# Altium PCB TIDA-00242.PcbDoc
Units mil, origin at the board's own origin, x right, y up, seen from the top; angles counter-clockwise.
Board outline 1000 x 1000 mil, 2 copper layers (Top Layer, Bottom Layer), stack 40.8 mil thick; 41 components, 18 nets, 113 pads, 38 vias.
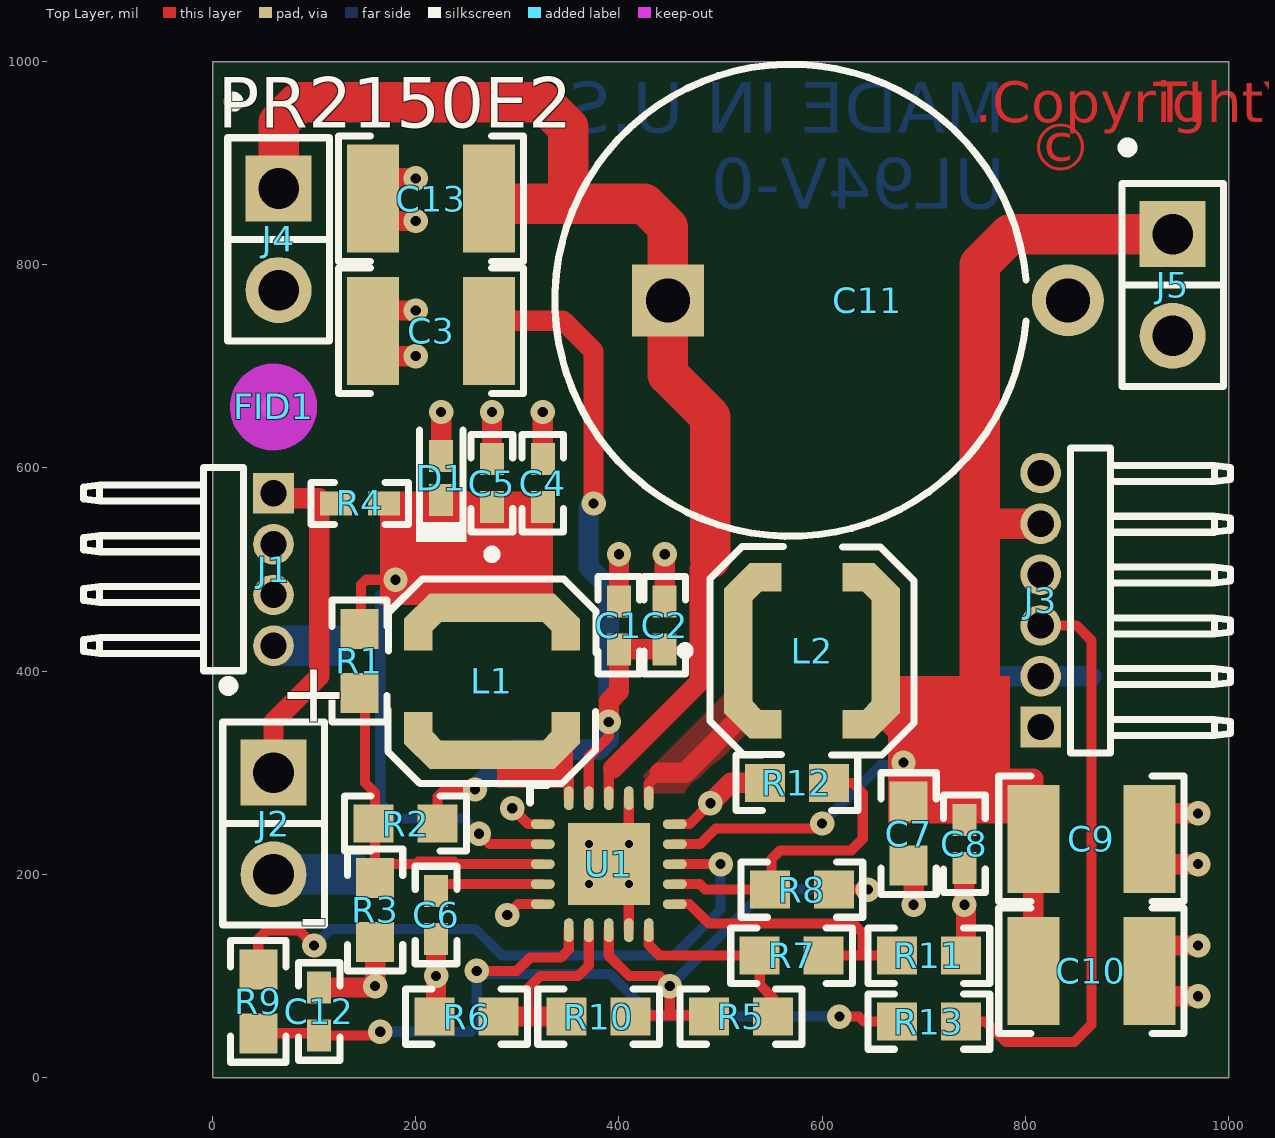
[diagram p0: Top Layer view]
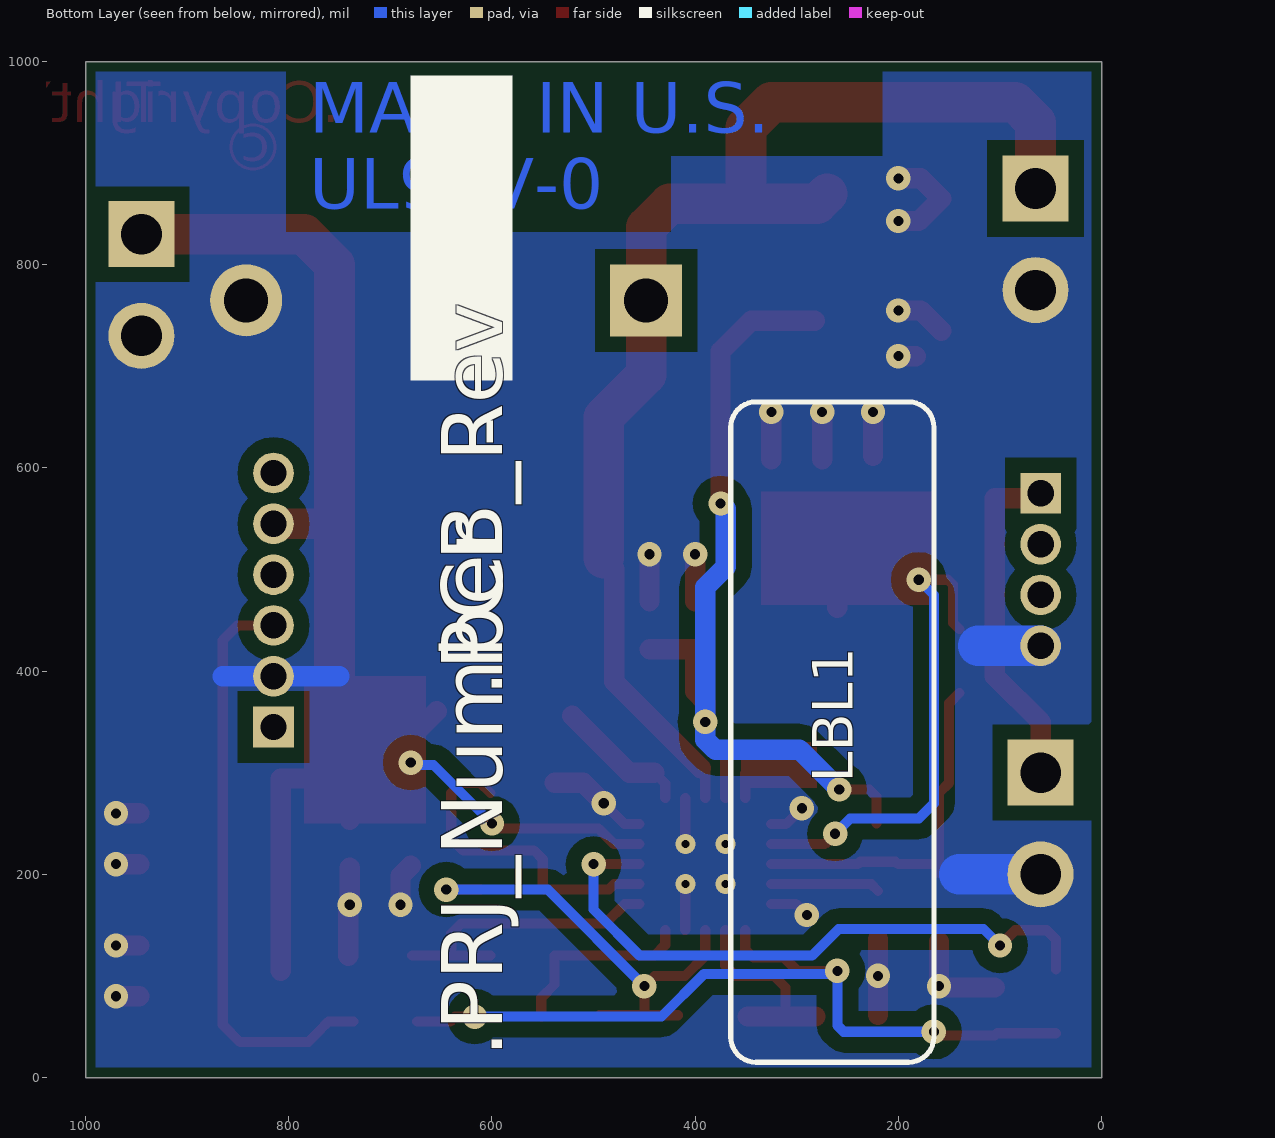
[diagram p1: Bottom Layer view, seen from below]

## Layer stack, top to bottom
Top Layer: signal copper 1.4
Dielectric: core 38, FR-4, Dk 4.8
Bottom Layer: signal copper 1.4

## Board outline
0,0 0,1000 1000,1000 1000,0 0,0

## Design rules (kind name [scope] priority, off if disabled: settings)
AcuteAngle [All] p1: minimum=4.50000000000000E+0001 checktracksonly=FALSE
AssemblyTestPointUsage [All] p1: valid=2
Clearance Clearance_BoardEdge_MountingHoles [OnCopper and InComponentClass('Mounting Holes') vs IsKeepOut] p1: gap=20
Clearance Clearance_BoardEdge_Poly [OnCopper and InPoly vs IsKeepOut] p2: gap=25
Clearance Clearance_BoardEdge [OnCopper and Not InComponentClass('Logo') and not InComponentClass('FiducialMark') and not InRegion(1000,500,4000,800) and Not IsKeepout vs IsKeepOut] p3: gap=20
Clearance Clearance_Poly [InPolygon] p4: gap=15
Clearance [All] p5: gap=8
ComponentClearance ComponentClearance_Logo [InComponentClass('Logo')] p1: gap=20 collisioncheckmode=3 verticalgap=10 showdistances=FALSE
ComponentClearance ComponentClearance_ScrewToNut [(HasFootprint('NY PMS 440 0025 PH')) vs (HasFootprint('Keystone_1902C'))] p2: gap=10 collisioncheckmode=3 verticalgap=10 showdistances=FALSE
ComponentClearance ComponentClearance_MountingHoles [InComponentClass('Mounting Holes')] p3: gap=20 collisioncheckmode=3 verticalgap=100000 showdistances=FALSE
ComponentClearance ComponentClearance_SmallPassives [HasFootprint('0201*') or HasFootprint('0402*') or HasFootprint('0508') or HasFootprint('0603*') or HasFootprint('0612') or HasFootprint('0805*') or HasFootprint('0815*') or HasFootprint('0830*') or HasFootprint('1206*') or HasFootprint('1210*') or HasFootprint('1808*') or HasFootprint('1812*') or HasFootprint('1825*') or HasFootprint('2010*') or HasFootprint('2220*') or HasFootprint('2225*') or HasFootprint('2512*') or HasFootprint('2728*') or HasFootprint('3518*') vs HasFootprint('0201*') or HasFootprint('0402*') or HasFootprint('0508') or HasFootprint('0603*') or HasFootprint('0612') or HasFootprint('0805*') or HasFootprint('0815*') or HasFootprint('0830*') or HasFootprint('1206*') or HasFootprint('1210*') or HasFootprint('1808*') or HasFootprint('1812*') or HasFootprint('1825*') or HasFootprint('2010*') or HasFootprint('2220*') or HasFootprint('2225*') or HasFootprint('2512*') or HasFootprint('2728*') or HasFootprint('3518*')] p4: gap=20 collisioncheckmode=3 verticalgap=10 showdistances=FALSE
ComponentClearance ComponentClearance_THtoSMT [IsThruComponent vs IsSMTComponent] p5: gap=20 collisioncheckmode=3 verticalgap=20 showdistances=FALSE
ComponentClearance ComponentClearance_THtoTH [IsThruComponent vs IsThruComponent] p6: gap=20 collisioncheckmode=3 verticalgap=20 showdistances=FALSE
ComponentClearance [All] p7: gap=20 collisioncheckmode=3 verticalgap=10 showdistances=FALSE
DiffPairsRouting [All] p1: maxlimit=100 minlimit=10 mostfreqgap=10 maxuncoupledlength=1000
FabricationTestPointUsage TestPointUsage [All] p1: valid=2 allowmultiple=FALSE
FabricationTestpoint Testpoint [All] p1: side=3 testpointundercomponent=TRUE minsize=40 maxsize=100 preferedsize=60 minholesize=0 maxholesize=40 preferedholesize=32 testpointgrid=1 allowsidetop=TRUE allowsidebottom=TRUE usegrid=TRUE gridtolerance=0.01
FanoutControl Fanout_LCC [IsLCC] p1: bgadir=Out bgaviamode=Centered fanoutstyle=Auto fanoutdirection=Alternating viagrid=1 // Fanout_LCC (Default Rule)
FanoutControl Fanout_BGA [IsBGA] p2: bgadir=Out bgaviamode=Centered fanoutstyle=Auto fanoutdirection=Alternating viagrid=1 // Fanout_BGA (Default Rule)
FanoutControl Fanout_Default [All] p4: bgadir=Out bgaviamode=Centered fanoutstyle=Auto fanoutdirection=Alternating viagrid=1 // Fanout_Default (Default Rule)
FanoutControl Fanout_Small [(CompPinCount < 5)] p5: bgadir=Out bgaviamode=Centered fanoutstyle=Auto fanoutdirection=OutThenIn viagrid=1 // Fanout_Small (Default Rule)
HoleSize [All] p1: absolutevalues=TRUE maxlimit=251 minlimit=8 maxpercent=80.000 minpercent=20.000
MinimumAnnularRing [All] p1: minimumring=9
MinimumSolderMaskSliver MinimumSolderMaskSliver_Logo [InComponentClass('Logo') vs InComponentClass('Logo')] p1: minsoldermaskwidth=0.7
MinimumSolderMaskSliver [All] p2: minsoldermaskwidth=4
PlaneConnect [All] p1: planeconnectstyle=Relief reliefexpansion=10 reliefentries=4 reliefconductorwidth=10 reliefairgap=10
PolygonConnect [All] p1: connectstyle=Direct reliefconductorwidth=10 reliefentries=4 polygonreliefangle="90 Angle" airgapwidth=10
RoutingVias [All] p1: holewidth=16 width=34 viastyle="Through Hole" minholewidth=8 minwidth=26 maxholewidth=40 maxwidth=65
SMDToCorner [All] p1: distance=30000
SilkToSilkClearance [All] p1: silktosilkclearance=5
SilkscreenOverComponentPads [All] p1: minsilkscreentomaskgap=5
SolderMaskExpansion [All] p1: expansion=3
Width [All] p1: maxlimit=100 minlimit=6 preferedwidth=10 checkconnectedcopper=TRUE
14 further rules are at their usual default settings.

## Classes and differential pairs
component class "PR2150E2 sheet 2": C1 C2 C3 C5 C6 C7 C8 C9 C10 C11 C12 C13 D1 J1 J2 J3 J4 J5 L1 L2 R1 R2 R3 R4 R5 R6 R7 R8 R9 R10 R11 R13 U1
component class "PR2150E2 sheet 3": FID1 LBL1 ZZ1 ZZ2 ZZ3 ZZ4
component class FiducialMark: FID1
component class AssemblyNote: ZZ1 ZZ2 ZZ3 ZZ4
component class Label: LBL1

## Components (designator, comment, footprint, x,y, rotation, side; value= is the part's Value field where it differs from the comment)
C1 "C1005X5R0J475M050BC" 0402 400,445 r90 top
C2 "GRM155R71A104KA01D" 0402 445,445 r90 top
C3 "C1210C107M9PACTU" 1210 215,735 r180 top (schematic designator C4)
C4 "GRM155R71A104KA01D" 0402 325,585 r90 top
C5 "C1005X5R0J475M050BC" 0402 275,585 r90 top
C6 "GRM155R61A103KA01D" 0402 220,160 r270 top
C7 "CL10A226MP8NUNE" 0603 685,240 r270 top
C8 "GRM155R71A104KA01D" 0402 740,230 r270 top
C9 "C1210C107M9PACTU" 1210 865,235 r0 top
C10 "C1210C107M9PACTU" 1210 865,105 r0 top
C11 "DX-5R5H473U" DX-H_1150x500 645,765 r0 top
C12 "C1005X5R0J105M" 0402 105,65 r90 top
C13 "C1210C107M9PACTU" 1210 215,865 r180 top
D1 "BZT52C4V7T-7" SOD-523 225,590 r90 top
FID1 "Fiducial" Fiducial6.4-20 60,660 r0 top
J1 "GRPB041VWCN-RC" Sullins_GRPB041VWCN 60,500 r270 top
J2 "90120-0122" CONN_90120-0122 60,250 r270 top
J3 "GRPB061VWCN-RC" Sullins_GRPB061VWCN 815,470 r90 top
J4 "90120-0122" CONN_90120-0122 65,825 r270 top
J5 "90120-0122" CONN_90120-0122 945,780 r270 top
L1 "LPS4018-223MLB" LPS4018 275,390 r270 top
L2 "LPS4018-103MLB" LPS4018 590,420 r0 top
LBL1 "Size: 0.65\" x 0.20 \"" Label_650x200 265,340 r90 bottom
R1 "ERJ-3GEY0R00V" 0603 144.61,409.87 r270 top
R2 "ERJ-3GEY0R00V" 0603 190,250 r0 top
R3 "ERJ-3GEY0R00V" 0603 160,165 r90 top
R4 "CRCW0402100RJNED" 0402 145,565 r0 top
R5 "CRCW06033M01FKEA" 0603 520,60 r180 top
R6 "CRCW06035M62FKEA" 0603 250,60 r0 top
R7 "CRCW06035M90FKEA" 0603 570,120 r180 top
R8 "CRCW06037M87FKEA" 0603 580,185 r0 top
R9 "CRCW06031M24FKEA" 0603 45,75 r90 top
R10 "CRCW06037M32FKEA" 0603 380,60 r0 top
R11 "CRCW06034M02FKEA" 0603 705,120 r180 top (schematic designator R12)
R12 "CRCW06035M36FKEA" 0603 575,290 r0 top
R13 "ERJ-3GEY0R00V" 0603 705,55 r0 top
U1 "BQ25570RGR" RGR0020A 390,210 r0 top
ZZ1 "This Assembly Note is for PCB labels only" AssemblyNoteLabel 205,2328 r0 top
ZZ2 "This Assembly Note will show in the PcbDoc and associated outputs" AssemblyNote 205,2219.11 r0 top
ZZ3 "This Assembly Note will show in the PcbDoc and associated outputs" AssemblyNote 205,2130.56 r0 top
ZZ4 "This Assembly Note will show in the PcbDoc and associated outputs" AssemblyNote 205,2042 r0 top

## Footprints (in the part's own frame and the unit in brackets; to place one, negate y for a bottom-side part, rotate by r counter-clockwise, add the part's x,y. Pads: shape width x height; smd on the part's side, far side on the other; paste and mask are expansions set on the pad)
0402 [mm] "0402 from SM-752 data"
  rect 0.8x0.6 smd: 1(-0.6,0) 2(0.6,0)
  silkscreen extent -1.22,-0.52 1.22,0.52, body extent -0.55,-0.3 0.55,0.3, height 0.6
0603 [mm] "0603 from SM-752 data"
  rect 1x0.95 smd: 1(-0.8,0) 2(0.8,0)
  silkscreen extent -1.52,-0.69 1.52,0.69, body extent -0.87,-0.47 0.87,0.47, height 0.85
1210 [mm] "1210 from SM-752 data"
  rect 1.3x2.7 smd: 1(-1.45,0) 2(1.45,0)
  silkscreen extent -2.32,-1.57 2.32,1.57, body extent -1.7,-1.35 1.7,1.35, height 1.35
AssemblyNote [mil] "Assembly Note"
AssemblyNoteLabel [mil] "Assembly Note for PCB Labels"
CONN_90120-0122 [mm] "Molex"
  rect 1.65x1.65 hole 1.016 mask+0: 1(-1.27,0)
  round 1.65 hole 1.016 mask+0: 2(1.27,0)
  silkscreen extent -3.56,-1.27 2.54,1.27, body extent -2.54,-1.27 2.54,1.27, height 9.29
DX-H_1150x500 [mm] "Elna horizontal SUPERCAP"
  rect 1.8x1.8 hole 1.1: 1(-5,0)
  round 1.8 hole 1.1: 2(5,0)
  silkscreen extent -7.82,-5.9 3.95,5.9, body extent -7.84,-5.91 5.07,5.91, height 5.5
Fiducial6.4-20 [mil]
  round 25 smd paste-12.5 mask+26.87: 1(0,0)
  Top Layer keep-out circle w46.37: c0,0 r19.68
Label_650x200 [mil] "Thermal Transfer Label"
  round 1 on Mech14: 0(0,0)
  silkscreen extent -325,-100 325,100, body extent -326,-101 326,101, height 1
LPS4018 [mil]
  rect 28x123 smd: 1(-72.5,0) 2(72.5,0)
  rect 35.5x28 smd rot 45: 1(-64,64) 2(64.5,-63.5)
  rect 35.5x28 smd rot 135: 1(-64,-64) 2(64,64)
  rect 31.5x28 smd: 1(-46,72.5) 1(-46,-72.5) 2(46,72.5) 2(46,-72.5)
  silkscreen extent -129,-102 101,102, body extent -81,-81 81,81, height 71
RGR0020A [mm] "QFN, 20-Leads, Body 3.5x3.5mm, Pitch 0.5mm, Thermal Pad 2.05x2.05mm, TI Recommended"
  oval 0.6x0.24 smd paste-0.025 mask+0.07: 1(-1.65,1) 2(-1.65,0.5) 3(-1.65,0) 4(-1.65,-0.5) 5(-1.65,-1) 11(1.65,-1) 12(1.65,-0.5) 13(1.65,0) 14(1.65,0.5) 15(1.65,1)
  oval 0.24x0.6 smd paste-0.025 mask+0.07: 6(-1,-1.65) 7(-0.5,-1.65) 8(0,-1.65) 9(0.5,-1.65) 10(1,-1.65) 16(1,1.65) 17(0.5,1.65) 18(0,1.65) 19(-0.5,1.65) 20(-1,1.65)
  rect 2.05x2.05 smd paste-1.025 mask+0.07: 21(0,0)
  silkscreen extent -1.97,1.54 -1.54,1.97, body extent -1.83,-1.83 1.83,1.83, height 1.01
SOD-523 [mm] "NXP Semiconductor recommended land pattern, nominal STEP model"
  rect 0.8x0.6 smd paste-0.05: 1(-0.55,0) 2(0.55,0)
  silkscreen extent -1.6,-0.64 1.2,0.63, body extent -0.8,-0.4 0.8,0.4, height 0.72
Sullins_GRPB041VWCN [mil] "Sullins"
  rect 40x40 hole 26 mask+3: 1(-75,0)
  round 40 hole 26 mask+3: 2(-25,0) 3(25,0) 4(75,0)
  silkscreen extent -100,-187 100,-30, body extent -100,-187 100,8, height 85
Sullins_GRPB061VWCN [mil] "Sullins"
  rect 40x40 hole 26 mask+3: 1(-125,0)
  round 40 hole 26 mask+3: 2(-75,0) 3(-25,0) 4(25,0) 5(75,0) 6(125,0)
  silkscreen extent -150,-187 150,-30, body extent -150,-187 150,8, height 85

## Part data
C1 C5: "CAP, CERM, 4.7uF, 6.3V, +/-20%, X5R, 0402"
C2 C4 C8: "CAP, CERM, 0.1uF, 10V, +/-10%, X7R, 0402"
C3 C9 C10 C13: "CAP, CERM, 100uF, 6.3V, +/-20%, X5R, 1210"
C6: "CAP, CERM, 0.01uF, 10V, +/-10%, X5R, 0402"
C7: "CAP, CERM, 22uF, 10V, +/-20%, X5R, 0603"
C11: "CAP, Electric Double Layer, 47000uF, 5.5V, +80/-20%, TH"
C12: "CAP, CERM, 1uF, 6.3V, +/-20%, X5R, 0402"
D1: "Diode, Zener, 4.7V, 300mW, SOD-523"
FID1: "Fiducial mark.  There is nothing to buy or mount."
J1: "Header, 50mil, 4x1, R/A, TH"
J2 J4 J5: "Header, 100mil, 2x1, Tin plated, TH"
J3: "Header, 50mil, 6x1, R/A, TH"
L1: "Inductor, Shielded Drum Core, Ferrite, 22uH, 0.83A, 0.36 ohm, SMD"
L2: "Inductor, Shielded Drum Core, Ferrite, 10uH, 1.25A, 0.2 ohm, SMD"
LBL1: library part THT-14-423-10, "Thermal Transfer Printable Labels, 0.650\" W x 0.200\" H - 10,000 per roll"
R1 R2 R3 R13: "RES, 0 ohm, 5%, 0.1W, 0603"
R4: "RES, 100 ohm, 5%, 0.063W, 0402"
R5: "RES, 3.01Meg ohm, 1%, 0.1W, 0603"
R6: "RES, 5.62Meg ohm, 1%, 0.1W, 0603"
R7: "RES, 5.90Meg ohm, 1%, 0.1W, 0603"
R8: "RES, 7.87Meg ohm, 1%, 0.1W, 0603"
R9: "RES, 1.24Meg ohm, 1%, 0.1W, 0603"
R10: "RES, 7.32Meg ohm, 1%, 0.1W, 0603"
R11: "RES, 4.02Meg ohm, 1%, 0.1W, 0603"
R12: "RES, 5.36Meg ohm, 1%, 0.1W, 0603"
U1: "Ultra Low Power Harvester Power Management IC with Boost Charger, and Nano-Powered Buck Converter, RGR0020A"
ZZ1: library part AssemblyNoteLabel
ZZ2 ZZ3 ZZ4: library part AssemblyNote

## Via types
v1: diameter 24, hole 10, Top Layer to Bottom Layer, tented both sides, 34 vias
v2: diameter 19.68, hole 7.87, Top Layer to Bottom Layer, 4 vias

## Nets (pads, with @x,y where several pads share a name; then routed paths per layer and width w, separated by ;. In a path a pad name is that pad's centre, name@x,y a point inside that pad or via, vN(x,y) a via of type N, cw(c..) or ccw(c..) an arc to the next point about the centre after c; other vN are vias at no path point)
GND: C1.2 C2.2 C3.2 C4.2 C5.2 C6.2 C7.2 C8.2 C9.2 C10.2 C11.2 C12.2 C13.2 D1.2 J1.4 J2.2 J3.2 J4.2 J5.2 R3.1 R6.1 R11.1 R12.1 U1.1 U1.5 U1.9 U1.15 U1.17 U1.21 | length 1321.3
  Top Layer w10: v1(290,160) 300.63,170.63 U1.5 ; v1@290,270 v1(295,265) 310.63,249.37 U1.1 ; U1.9 v2(409.68,190.32) ; v2(409.68,229.68) U1.17 ; U1.15 469.37,249.37 v1(490,270)
  Top Layer w20: C12.2 158.62,88.62 v1(160,90) R3.1 ; C3.2 177.91,755 v1(200,755) ; C3.2@182.91,710 v1(200,710) ; v1(200,842.99) 179.92,842.99 C13.2 177.91,885 v1(200,885) ; R6.1@220,61.5 v1(220,100) C6.2 ; D1.2 v1(225,655) ; C5.2 v1(275,655) ; C4.2 v1(325,655) ; C1.2 v1(400,515) ; C2.2 v1(445,515) ; v1(490,270) 510,290 R12.1@538.5,290 ; C7.2@680,208.5 690,198.5 v1(690,170) ; v1(740,170) C8.2 ; R11.1@741.5,120 v1@741.5,168.5 ; C10.2@947.09,80 v1(970,80) ; C10.2@947.09,130 v1(970,130) ; C9.2@947.09,210 v1(970,210) ; C9.2@947.09,260 v1(970,260)
  Bottom Layer w20: 750,395 J3.2 865,395
  Bottom Layer w40: J2.2 140,200 ; J1.4 121.3,425
  other v2: 370.32,190.32 370.32,229.68
NetC1_1: C1.1 C2.1 C3.1 R2.2 U1.19 | length 913
  Top Layer w10: R2.2 221.5,276.5 228.5,283.5 v1(258.25,283.5) ; U1.19 370.31,315.81 390,335.5 v1(390,350)
  Top Layer w20: C3.1@282.09,745 345,745 375,715 v1(375,565) ; v1(390,350) 390,370 400,380 C1.1 C2.1
  Bottom Layer w20: v1(258.25,283.5) 297.25,322.5 380,322.5 390,332.5 v1(390,350) 390,482.57 370,502.57 v1@370,560
NetC4_1: C4.1 C5.1 D1.1 L1.1 R1.1 R4.2 U1.2 | length 513.2
  Top Layer w10: R1.1@140,441.5 146.16,447.66 146.16,485 151.16,490 v1(180,490) ; 258.21,490 260,488.21 ; v1(262.3,240) 272.61,229.69 U1.2
  Top Layer w20: L1.1@260,462.5 260,488.21
  Bottom Layer w10: v1(180,490) 165,475 165,270 180,255 247.3,255 v1(262.3,240)
NetC6_1: C6.1 U1.4 | length 107.8
  Top Layer w10: C6.1 226.69,190.32 U1.4
NetC7_1: C7.1 C8.1 C9.1 C10.1 J3.5 J5.1 L2.2 U1.14 | length 1458
  Top Layer w10: U1.14 479.69,229.69 495,245 599,245 v1@600,246
  Top Layer w20: L2.2@654.5,360.5 676.5,338.5 680,338.5 v1(680,310) ; C7.1@680,271.5 v1(680,310) ; C8.1 740,290 ; C10.1 C9.1 807.91,294.32 744.32,294.32 740,290 ; v1(680,310) 690,300 730,300 740,290
  Top Layer w30: 770,545 J3.5
  Top Layer w40: 760,310 755,315 755,800 785,830 J5.1
  Bottom Layer w10: v1(600,250) 657.57,307.57 v1@677.57,307.57
NetC11_1: C11.1 C13.1 J4.1 U1.18 | length 1256.2
  Top Layer w10: U1.18 390,300 394.5,304.5
  Top Layer w20: 394.5,304.5 479.5,389.5 479.5,500.75 490,511.25
  Top Layer w40: J4.1 65,940 85,960 325,960 350,935 350,860 ; C13.1@270,870 280,860 350,860 ; 490,511.25 490,650 448.15,691.85 C11.1 448.15,836.85 425,860 350,860
NetC12_1: C12.1 R9.1 R13.1 U1.6 | length 816.2
  Top Layer w10: R9.1 102.87,43.5 C12.1 161.38,41.38 v1(165,45) ; v1@270,105 299.54,105 312.54,118 342.54,118 350.63,126.09 U1.6 ; v1(616.95,60) 636.21,60 641.21,55 R13.1
  Bottom Layer w10: v1(165,45) 253.7,45 260,51.3 v1(260,105) 263,102 391.15,102 433.15,60 v1(616.95,60)
NetJ1_1: J1.1 J2.1 R4.1 | length 350.7
  Top Layer w10: J1.1 75,575 80,570
  Top Layer w20: J2.1 60,350 105,395 105,570 80,570 J1.1@65,570
NetJ3_3: J3.3 R13.2 | length 578.4
  Top Layer w10: R13.2 761.02,55 769.32,46.7 769.32,46.47 780.79,35 848.15,35 865,51.85 865,430.3 850.3,445 J3.3
NetL1_2: L1.2 U1.20 | length 46.5
  Top Layer w10: 345,305 350.63,299.37 U1.20
  Top Layer w20: L1.2@335,315 345,305
NetL2_1: L2.1 U1.16 | length 133.6
  Top Layer w10: U1.16 429.37,289.37 440,300
  Top Layer w20: 440,300 465,300 L2.1@521,356
NetR1_2: R1.2 R2.1 R3.2 U1.3 | length 343.8
  Top Layer w10: R1.2@140,378.5 150,368.5 150,290 160,280 R3.2@160,201.5 ; R3.2@168.5,210 200.43,210 202.8,212.37 237.63,212.37 240,210 U1.3
NetR5_1: R5.1 R7.2 U1.10 | length 193.3
  Top Layer w10: U1.10 429.37,130.63 440,120 R7.2 538.5,91.5 551.5,78.5 R5.1
NetR5_2: R5.2 R8.2 R10.2 U1.8 | length 471
  Top Layer w10: U1.8 390,120 410,100 440,100 v1(450,90) 450,61.32 ; R10.2@417.07,61.32 450,61.32 ; R5.2@494.08,61.32 450,61.32 ; R8.2 v1(645,185)
  Bottom Layer w10: v1(450,90) 545,185 v1(645,185)
NetR6_2: R6.2 R10.1 U1.7 | length 198.6
  Top Layer w10: 311.02,60 311.02,88.54 322.48,100 360,100 370.31,110.31 U1.7
  Top Layer w20: R6.2 311.02,60 R10.1
NetR7_1: R7.1 R11.2 U1.11 | length 295.7
  Top Layer w10: U1.11 469.37,170.63 488.3,151.7 630,151.7 640,141.7 640,120 ; R7.1 668.5,120 R11.2@678.5,120
NetR8_1: R8.1 R12.2 U1.12 | length 316.4
  Top Layer w10: U1.12 479.68,190.32 485,185 R8.1 550,186.5 550,215 558.62,223.62 628.62,223.62 640,235 640,280 630,290 611.5,290 R12.2@601.5,280
NetR9_2: R9.2 U1.13 | length 620.5
  Top Layer w10: R9.2 45,136.02 53.98,145 85,145 v1(100,130) ; U1.13 v1(500,210)
  Bottom Layer w10: v1(100,130) 116.22,146.22 258.78,146.22 285,120 454.54,120 500,165.46 v1(500,210)
pads on no net: FID1.1 J1.2 J1.3 J3.1 J3.4 J3.6 LBL1.0

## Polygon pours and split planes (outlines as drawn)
GND on Bottom Layer "Bottom Layer-GND" (solid, remove dead copper, pour order 4): 10,15 10,990 990,990 990,10 10,10
NetL2_1 on Top Layer "Top Layer-No Net" (solid, remove dead copper, pour order 3): 511.6,380 505.92,380 420.72,297.25 420,296.55 420,280 465.44,280 466.16,280.7 540,352.42 540,357.93 528.64,357.93 505.92,380

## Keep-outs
Keep-Out Layer:
  text ".Layer_Name" at 577,-858.49 h60

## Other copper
Top Layer:
  rectangle net NetC4_1: 165,465 335,576.81
  rectangle net NetC7_1: 665,250 785,395
  rectangle net NetC7_1: 665,375 715,380
  rectangle net NetL1_2: 280,285 355,330
  text ".CopyrightYear" at 750,940 h40
  text "TI" at 926,940 h40
  text "©" at 803,877.48 h80
  text ".Layer_Name" at 577,-858.49 h60
Bottom Layer:
  text "MADE IN U.S." at 780,930 h50
  text "UL94V-0" at 780,855 h50
  text ".VersionControl_RevNumber" at 3891,179.5 h60
  text "SVN:" at 4170,179.5 h60
  text ".Layer_Name" at 577,-858.49 h60

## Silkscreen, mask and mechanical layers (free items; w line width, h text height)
Top Overlay:
  text "PR2150E2" at 5,935 h50
  text "+" at 65,350 h60
  text "-" at 84.99,130 h60
  text ".Layer_Name" at 577,-858.49 h60
Bottom Overlay:
  region: 580,986 580,686 680,686 680,986
  text "-" at 579.5,621 h60 r270
  text ".PCB_Rev" at 590,375 h60 r270
  text ".PRJ_Number" at 590,20 h60 r270
  text ".Layer_Name" at 577,-858.49 h60
Top Paste:
  text ".Layer_Name" at 577,-858.49 h60
Bottom Paste:
  text ".Layer_Name" at 577,-858.49 h60
Top Solder:
  text ".Layer_Name" at 577,-858.49 h60
  text ".Layer_Name" at 577,-858.49 h60
Bottom Solder:
  text ".Layer_Name" at 577,-858.49 h60
Drill Guide:
  text ".Layer_Name" at 577,-858.49 h60
M1 Board Outline:
  lines w10: -0.02,5 0,1000 ; 800,0 0,0 ; 1000,630 1000,0 ; 0,0 1000,0 ; 0,0 0,1000 ; 0,0 0,1000 ; 0,0 0,1000 ; 0,0 0,1000 ; 0,0 0,1000 ; 0,0 0,1000 ; 0,1000 1000,1000 1000,0
  text ".Layer_Name" at 577,-858.49 h60
M2 Board Dimensions:
  rectangle: -0.5,-285.5 124.5,-160.5
  rectangle: 124.5,-410.5 499.5,-285.5
  lines w7: -0.5,-285.5 999.5,-285.5 ; 124.5,-410.5 124.5,-160.5 ; 249.5,-410.5 249.5,-160.5 ; 499.5,-410.5 499.5,-160.5 ; 749.5,-410.5 749.5,-160.5 ; -0.5,-410.5 999.5,-410.5 999.5,-160.5 -0.5,-160.5 -0.5,-410.5
  lines w10: -0.5,-475.5 -0.5,-455.5 ; 59.5,-485.5 -0.5,-465.5 ; 59.5,-445.5 -0.5,-465.5 ; 223.58,-465.5 -0.5,-465.5 ; 775.42,-465.5 999.5,-465.5 ; 939.5,-485.5 999.5,-465.5 ; 939.5,-445.5 999.5,-465.5 ; 999.5,-475.5 999.5,-455.5
  text "1000 (mil)" at 233.58,-501.49 h60
  text ".Layer_Name" at 577,-858.49 h60
M3 3D STEP Top:
  text ".Layer_Name" at 577,-858.49 h60
M4 3D STEP Bottom:
  text ".Layer_Name" at 577,-858.49 h60
M5 Assembly Top:
  lines w7: 1619,895.5 2744,895.5 ; 1619,1018 2741.5,1018 ; 1934,775.5 1934,1138 ; 2319,775.5 1619,775.5 ; 2319,1138 1619,1138 ; 1619,775.5 2744,775.5 2744,1138 1619,1138 ; 1619,775.5 1619,1138
  lines w10: -292,-930.17 6308,-930.17 ; -292,-726.83 6310,-726.83 ; -292,-523.5 -292,-1133.5 3713,-1133.5 6310,-1133.5 6310,-523.5 -291.5,-523.5 -291.5,-1133.5 1284,-1133.5 ; 2173,-1133.5 2173,-523.5 ; 3440,-726.83 3440,-523.5 ; 4280,-726.83 4280,-523.5 ; 4902,-1140 4902,-937.17
  text "TABLE 1" at 2006.5,1173 h40
  text "Variant" at 1644,1063 h40
  text "Label text" at 2079,1063 h40
  text "001" at 1711.5,943 h40
  text "ChangeMe!" at 1989,940.5 h40
  text "002" at 1711.5,818 h40
  text "ChangeMe!" at 1984,815.5 h40
  text "COMPONENTS MARKED 'DNP' SHOULD NOT BE POPULATED." at 1153.5,-318.5 h60
  text "ASSEMBLY VARIANT:" at 1153,-434 h60
  text ".VariantName" at 2189,-434 h60
  text "PCB VIEWED FROM TOP SIDE" at -228.5,-655.67 h60
  text "BOARD #:" at 2248,-655.67 h60
  text ".PRJ_Number" at 2793.5,-655.67 h60
  text "REV:" at 3638,-655.67 h60
  text ".PCB_Rev" at 3929.5,-655.67 h60
  text "SVN REV:" at 4476,-655.67 h60
  text ".VersionControl_RevNumber" at 4982,-655.67 h60
  text "IGNORE ->" at -228.5,-858.49 h60
  text "PLOT NAME =" at -228.5,-1064.34 h60
  text ".plot_File_Name" at 577,-1064.34 h60
  text "GENERATED    :" at 2250,-1064.34 h60
  text ".Print_Date" at 3119.5,-1064.34 h60
  text ".Print_Time" at 3848.5,-1064.34 h60
  text "TEXAS INSTRUMENTS" at 5113,-1064.34 h60
M6 Assembly Bottom:
  lines w10: -292.5,-727.33 6309.5,-727.33 ; -290.5,-930.67 6309.5,-930.67 ; 1115.5,-1140.5 1115.5,-937.67 ; 1737.5,-727.33 1737.5,-524 ; 2577.5,-727.33 2577.5,-524 ; 3844.5,-1134 3844.5,-524 ; 4733.5,-1134 6309,-1134 6309,-524 -292.5,-524 -292.5,-1134 2304.5,-1134 6309.5,-1134 6309.5,-524
  text "COMPONENTS MARKED 'DNP' SHOULD NOT BE POPULATED." at 6102,-318 h60
  text ".VariantName" at 5058,-434 h60
  text "ASSEMBLY VARIANT:" at 6097,-434 h60
  text ".VersionControl_RevNumber" at 1035.5,-656.17 h60
  text "SVN REV:" at 1541.5,-656.17 h60
  text ".PCB_Rev" at 2088,-656.17 h60
  text "REV:" at 2379.5,-656.17 h60
  text ".PRJ_Number" at 3224,-656.17 h60
  text "BOARD #:" at 3769.5,-656.17 h60
  text "PCB VIEWED FROM BOTTOM SIDE" at 6246,-656.17 h60
  text "IGNORE ->" at 2547.85,-858.49 h60
  text "TEXAS INSTRUMENTS" at 904.5,-1064.84 h60
  text ".Print_Time" at 2169,-1064.84 h60
  text ".Print_Date" at 2898,-1064.84 h60
  text "GENERATED    :" at 3767.5,-1064.84 h60
  text ".plot_File_Name" at 5440.5,-1064.84 h60
  text "PLOT NAME =" at 6246,-1064.84 h60
M9 Title Sheet:
  drawing of 57 lines, arcs and shapes, not listed
  text "1" at 739.84,8036.5 h70
  text "2" at 3235.5,8036.5 h70
  text "3" at 5724.84,8036.5 h70
  text "4" at 8231.51,8036.5 h70
  text "5" at 10730.5,8036.5 h70
  text "6" at 13235.5,8036.5 h70
  text "A" at -416.5,6893.5 h70
  text "A" at 14383.5,6893.5 h70
  text "B" at -416.5,4513.5 h70
  text "B" at 14383.5,4513.5 h70
  text "C" at -416.5,2138.5 h70
  text "C" at 14383.5,2138.5 h70
  text "PROJECT TITLE:" at 11343.5,277.5 h45
  text ".PRJ_Title" at 11393.5,144.17 h70
  text "DESIGNED FOR:" at 11343.5,-23.5 h45
  text ".PRJ_Customer" at 11393.5,-163.5 h70
  text "D" at -416.5,-231.5 h70
  text "D" at 14383.5,-231.5 h70
  text "FILE NAME:" at 11343.5,-323.5 h45
  text ".PCB_File_Name_No_Path" at 11393.5,-443.5 h70
  text "Texas Instruments (TI) and/or its licensors do not warrant the accuracy or completeness of this specification" at 6374,-605.34 h45
  text "ENGINEER:" at 11343.5,-613.5 h45
  text "LAYOUT BY:" at 12848.5,-613.5 h45
  text "or any information contained therein. TI and/or its licensors do not warrant that this design will meet" at 6329.01,-718 h45
  text ".PRJ_Engineer" at 11393.5,-768.49 h70
  text ".PCB_Layout" at 12899,-768.49 h70
  text "the specifications, will be suitable for your application or fit for any particular purpose, or will operate in" at 6329.01,-830.67 h45
  text ".Layer_Name" at 577,-858.49 h60
  text "ALTIUM DESIGNER VERSION:" at 12848.5,-923.5 h45
  text "an implementation. TI and/or its licensors do not warrant that the design is production worthy. You should" at 6329.01,-943.33 h45
  text "completely validate and test your design implementation to confirm the system functionality for your application." at 6374,-1056 h45
  text ".print_Scale" at 11393.5,-1056.83 h70
  text ".Application_BuildNumber" at 12899,-1056.83 h70
  text "1" at 739.84,-1263.5 h70
  text "2" at 3235.5,-1263.5 h70
  text "3" at 5724.84,-1263.5 h70
  text "4" at 8231.51,-1263.5 h70
  text "5" at 10730.5,-1263.5 h70
  text "6" at 13235.5,-1263.5 h70
M10 Fab Notes:
  drawing of 212 lines, arcs and shapes, not listed
  text "DESIGN INFORMATION" at 12381.02,6810 h60
  text "(REFER ALSO ARRAY/PANEL PROFILING INFORMATION)" at 12019.46,6648.29 h60
  text "BOARD SIZE" at 11333.46,6644 h60
  text "1000MIL" at 11795.78,6516.18 h60
  text "X" at 12301.46,6516.18 h60
  text "900MIL" at 12532.78,6516.18 h60
  text "Number of Layers :" at 11736.46,6319 h60
  text "2" at 12831.27,6309 h60
  text "MIN. TRACK WIDTH:" at 11736.46,6180 h60
  text "8" at 12832.7,6180 h60
  text "MIL" at 12987.46,6180 h60
  text "MIN. CLEARANCE:" at 11736.46,6048 h60
  text "8" at 12832.7,6048 h60
  text "MIL" at 12987.46,6048 h60
  text "MIN. VIA PAD SIZE:" at 11736.46,5916 h60
  text "24" at 12802.71,5916 h60
  text "MIL" at 12987.46,5916 h60
  text "0.05mm (2MIL)" at 12431.46,5774.29 h60
  text "MINIMUM ANNULAR RING" at 11407.23,5770 h60
  text "EXTERNAL" at 13139.46,5770 h60
  text "PER" at 11607.23,5652 h60
  text "IPC-D-275 CLASS 2 LEVEL C" at 11827.23,5652 h60
  text "MIL, HOLES" at 13315.46,5539.71 h60
  text "+/-" at 12923,5539 h60
  text "+/-" at 13777,5539 h60
  text "REGISTRATION TOLERANCES:" at 11407.23,5534 h60
  text "METAL" at 12607,5534 h60
  text "5" at 13183.2,5534 h60
  text "3" at 14016.2,5534 h60
  text "MIL" at 14132.46,5534 h60
  text "MATERIAL:" at 11332.46,5324.54 h60
  text "FR-4 High Tg" at 12318.9,5184.21 h60
  text "FR-408" at 11753.46,5175.64 h60
  text "X" at 12165.46,5175.64 h60
  text "OTHER" at 13241.46,5175.64 h60
  text "38MIL" at 13693.46,5013.64 h60
  text "62 MIL (1.6mm) +/-10%" at 12073.56,5012.92 h60
  text "X" at 13230,5010 h60
  text "THICKNESS:" at 11407.23,5008.64 h60
  text "OTHER" at 13358.46,5008.64 h60
  text "TOLERANCE:" at 11407.23,4850.64 h60
  text "X" at 12246.53,4850.64 h60
  text "ANSI IPC-6012 TYPE 3 CLASS 2" at 12433.48,4850.64 h60
  text "OTHER +/-" at 12433.46,4694.64 h60
  text "BOW & TWIST:" at 11407.23,4537.64 h60
  text "X" at 12246.53,4537.64 h60
  text "ANSI IPC-6012 TYPE 3 CLASS 2" at 12433.48,4537.64 h60
  text "OTHER +/-" at 12433.46,4379.13 h60
  text "COPPER THICKNESS (FINISHED):" at 11332.46,4243.64 h60
  text "1.4MIL (1oz)" at 12212.46,4090.92 h60
  text "2MIL (1.4oz)" at 12979.46,4090.92 h60
  text "2.8MIL (2oz)" at 13706.46,4090.92 h60
  text "OUTER:" at 11689.46,4086.64 h60
  text "X" at 12084,4086 h60
  text "1.4MIL (1oz)" at 12212.46,3933.92 h60
  text "2.8MIL (2oz)" at 12979.46,3933.92 h60
  text "N/A" at 13706,3934.29 h60
  text "INNER SIGNAL:" at 11400.38,3929.64 h60
  text "X" at 12085.42,3929.64 h60
  text "DRILLING:" at 11332.46,3790.64 h60
  text "REFERENCE:" at 11407.23,3673.64 h60
  text "X" at 12055.46,3673.64 h60
  text "AS SHOWN" at 12242.46,3673.64 h60
  text "X" at 12956.46,3673.64 h60
  text "NC_DRILL FILES" at 13093.46,3673.64 h60
  text "PTH MIN COPPER THICKNESS:" at 11407.23,3515.64 h60
  text "X" at 12757.46,3515.64 h60
  text "1MIL" at 12894.46,3515.64 h60
  text "OTHER" at 13391.46,3515.64 h60
  text "BOARD FINISH:" at 11332.46,3356.64 h60
  text "SILKSCREEN:" at 11487.68,3238.64 h60
  text "X" at 12436.46,3238.64 h60
  text "TOP" at 12562.46,3238.64 h60
  text "X" at 12946.46,3238.64 h60
  text "BOTTOM" at 13073.46,3238.64 h60
  text "SILKSCREEN COLOR:" at 11487.68,3071.64 h60
  text "X" at 12435.42,3071.64 h60
  text "WHITE" at 12562.46,3071.64 h60
  text "OTHER" at 13073.46,3071.64 h60
  text "SOLDER RESIST COLOR:" at 11487.68,2901.64 h60
  text "X" at 12055.42,2742.44 h60
  text "GREEN" at 12182.46,2742.44 h60
  text "BLUE" at 12773.46,2742.44 h60
  text "OTHER" at 13311.46,2742.44 h60
  text "IMMERSION GOLD (ENIG)" at 12393.46,2553.92 h60
  text "ENEPIG" at 13731,2550.64 h60
  text "SURFACE FINISH:" at 11332.46,2549.64 h60
  text "X" at 12206.51,2549.64 h60
  text "IMM. TIN/SILVER OR EQUIV" at 11662,2392.64 h60
  text "OTHER" at 13093.46,2392.64 h60
  text "ARRAY/PANEL:" at 11332.46,2213.64 h60
  text "X" at 12200,2210 h60
  text "CUT AND TRIM PER MECH LAYER 1" at 12393.46,2209.35 h60
  text "N.C. ROUTE" at 12393.46,2057.64 h60
  text "V. SCORE" at 13259.46,2057.64 h60
  text "CERTIFICATION:" at 11332.46,1920.64 h60
  text "MATERIALS AND WORKMANSHIP FOR ALL PCBS" at 12057.46,1920.64 h60
  text "TO MEET OR EXCEED THE REQUIREMENTS OF:" at 12057.46,1822.64 h60
  text "X" at 11683.96,1686.13 h60
  text "ANSI IPC-A-600F CLASS ->" at 11822.96,1686.13 h60
  text "X" at 13462.02,1686.13 h60
  text "2" at 13580.96,1686.14 h60
  text "1" at 13265.96,1684.64 h60
  text "3" at 13934.96,1684.64 h60
  text "X" at 11686.02,1526.64 h60
  text "UL 94V-0" at 11822.96,1526.64 h60
  text "X" at 12498.02,1526.64 h60
  text "RoHS" at 12634.96,1526.64 h60
  text "OTHER" at 13279.36,1526.64 h60
  text "PER ORDER" at 13676.42,1526.64 h60
  text "ADDITIONAL REQUIREMENTS:" at 11332.46,1385.64 h60
  text "MICROSECTION:" at 11407.23,1270.64 h60
  text "YES" at 12312.96,1270.64 h60
  text "REQUIRED" at 13174.46,1114.49 h60
  text "BARE BOARD ELEC. TEST:" at 11407.23,1111.64 h60
  text "NONE" at 12712.96,1111.64 h60
  text "X" at 13047.46,1111.64 h60
  text "PER ORDER" at 13766.46,1111.64 h60
  text "MANUFACTURER'S UL:" at 11407.23,954.64 h60
  text "RAIL" at 12572.96,950.35 h60
  text "METAL" at 13064.77,950.35 h60
  text "X" at 13440,950 h60
  text "SILK" at 13576.46,950.35 h60
  text ".Layer_Name" at 577,-858.49 h60
M11 Gerber Information:
  lines w10: -292,-930.17 6308,-930.17 ; -292,-726.83 6310,-726.83 ; -292,-523.5 -292,-1133.5 3713,-1133.5 6310,-1133.5 6310,-523.5 -291.5,-523.5 -291.5,-1133.5 1284,-1133.5 ; 2173,-1133.5 2173,-523.5 ; 3440,-726.83 3440,-523.5 ; 4280,-726.83 4280,-523.5 ; 4902,-1140 4902,-937.17
  text "ALL ARTWORK VIEWED FROM TOP SIDE" at -228.5,-655.67 h60
  text "BOARD #:" at 2248,-655.67 h60
  text ".PRJ_Number" at 2793.5,-655.67 h60
  text "REV:" at 3638,-655.67 h60
  text ".PCB_Rev" at 3929.5,-655.67 h60
  text "SVN REV:" at 4476,-655.67 h60
  text ".VersionControl_RevNumber" at 4982,-655.67 h60
  text "LAYER NAME =" at -228.5,-858.49 h60
  text "PLOT NAME =" at -228.5,-1064.34 h60
  text ".plot_File_Name" at 577,-1064.34 h60
  text "GENERATED    :" at 2250,-1064.34 h60
  text ".Print_Date" at 3119.5,-1064.34 h60
  text ".Print_Time" at 3848.5,-1064.34 h60
  text "TEXAS INSTRUMENTS" at 5113,-1064.34 h60
M12 Stackup:
  lines w6: 11360,7460 13910,7460 ; 11360,7564.4 13910,7564.4 ; 11300,6975 ccw(c11334,6975) 11334,6941 13936,6941 ccw(c13936,6975) 13970,6975 13970,7681 ccw(c13936,7681) 13936,7715 11334,7715 ccw(c11334,7681) 11300,7681 11300,6975
  text "The Stackup Legend below this is static." at 11605.5,7874.5 h60
  text "If you change the stackup, update the Legend." at 11615.5,7784.5 h60
  text "Layer Stack Up Detail for: PR2150.PcbDoc" at 11360,7597.1 h57
  text "Layer" at 11360,7525.4 h24
  text "Gerber" at 12255.81,7525.4 h24
  text "Copper" at 12819.33,7525.4 h24
  text "Dielectric" at 13422.04,7525.4 h24
  text "Name" at 11360,7477.4 h24
  text "Document" at 12255.81,7477.4 h24
  text "Thickness" at 12819.33,7477.4 h24
  text "Material" at 13422.04,7477.4 h24
  text "Top Solder Mask" at 11360,7384.44 h34
  text "(.GTS)" at 12255.81,7384.44 h34
  text "Solder Resist" at 13422.04,7384.44 h34
  text "Top Layer" at 11360,7287.69 h34
  text "(.GTL)" at 12255.81,7287.69 h34
  text "1.4mil" at 12819.33,7287.69 h34
  text "FR-4" at 13422.04,7239.31 h34
  text "Bottom Layer" at 11360,7190.94 h34
  text "(.GBL)" at 12255.81,7190.94 h34
  text "1.4mil" at 12819.33,7190.94 h34
  text "Bottom Solder Mask" at 11360,7094.19 h34
  text "(.GBS)" at 12255.81,7094.19 h34
  text "Solder Resist" at 13422.04,7094.19 h34
  text ".Layer_Name" at 577,-858.49 h60
M13 Component Bodies Top:
  text ".Layer_Name" at 577,-858.49 h60
M14 Component Bodies Bottom:
  text ".Layer_Name" at 577,-858.49 h60
M15 Courtyards Top:
  text ".Layer_Name" at 577,-858.49 h60
M16 Courtyards Bottom:
  text ".Layer_Name" at 577,-858.49 h60
Drill Drawing:
  text ".legend" at 1602.5,1510.5 h60
  text "Drill Table" at 1627.5,1325.5 h60
  text ".Layer_Name" at 577,-858.49 h60

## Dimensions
0,0 to -10,1000 on M2 Board Dimensions
0,5 to 1000,0 on M2 Board Dimensions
